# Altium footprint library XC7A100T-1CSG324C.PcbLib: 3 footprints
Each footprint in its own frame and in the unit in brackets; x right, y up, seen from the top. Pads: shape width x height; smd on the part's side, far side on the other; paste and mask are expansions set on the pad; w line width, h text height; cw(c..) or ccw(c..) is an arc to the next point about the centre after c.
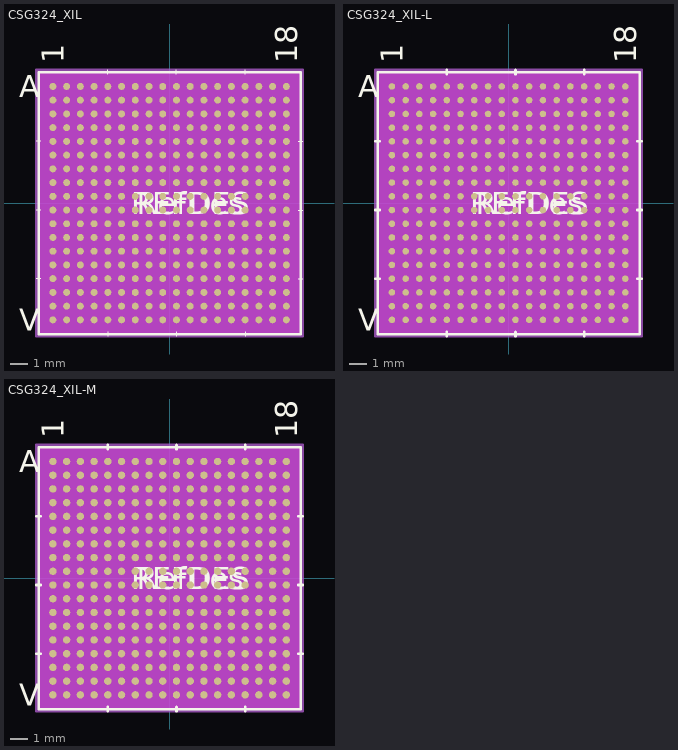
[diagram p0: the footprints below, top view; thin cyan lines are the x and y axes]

## CSG324_XIL [mm]
pads (324):
  round 0.406 smd paste+0 mask+0: A1(-6.8,6.8) A2(-6,6.8) A3(-5.2,6.8) A4(-4.4,6.8) A5(-3.6,6.8) A6(-2.8,6.8) A7(-2,6.8) A8(-1.2,6.8) A9(-0.4,6.8) A10(0.4,6.8) A11(1.2,6.8) A12(2,6.8) A13(2.8,6.8) A14(3.6,6.8) A15(4.4,6.8) A16(5.2,6.8) A17(6,6.8) A18(6.8,6.8) B1(-6.8,6) B2(-6,6) B3(-5.2,6) B4(-4.4,6) B5(-3.6,6) B6(-2.8,6) B7(-2,6) B8(-1.2,6) B9(-0.4,6) B10(0.4,6) B11(1.2,6) B12(2,6) B13(2.8,6) B14(3.6,6) B15(4.4,6) B16(5.2,6) B17(6,6) B18(6.8,6) C1(-6.8,5.2) C2(-6,5.2) C3(-5.2,5.2) C4(-4.4,5.2) C5(-3.6,5.2) C6(-2.8,5.2) C7(-2,5.2) C8(-1.2,5.2) C9(-0.4,5.2) C10(0.4,5.2) C11(1.2,5.2) C12(2,5.2) C13(2.8,5.2) C14(3.6,5.2) C15(4.4,5.2) C16(5.2,5.2) C17(6,5.2) C18(6.8,5.2) D1(-6.8,4.4) D2(-6,4.4) D3(-5.2,4.4) D4(-4.4,4.4) D5(-3.6,4.4) D6(-2.8,4.4) D7(-2,4.4) D8(-1.2,4.4) D9(-0.4,4.4) D10(0.4,4.4) D11(1.2,4.4) D12(2,4.4) D13(2.8,4.4) D14(3.6,4.4) D15(4.4,4.4) D16(5.2,4.4) D17(6,4.4) D18(6.8,4.4) E1(-6.8,3.6) E2(-6,3.6) E3(-5.2,3.6) E4(-4.4,3.6) E5(-3.6,3.6) E6(-2.8,3.6) E7(-2,3.6) E8(-1.2,3.6) E9(-0.4,3.6) E10(0.4,3.6) E11(1.2,3.6) E12(2,3.6) E13(2.8,3.6) E14(3.6,3.6) E15(4.4,3.6) E16(5.2,3.6) E17(6,3.6) E18(6.8,3.6) F1(-6.8,2.8) F2(-6,2.8) F3(-5.2,2.8) F4(-4.4,2.8) F5(-3.6,2.8) F6(-2.8,2.8) F7(-2,2.8) F8(-1.2,2.8) F9(-0.4,2.8) F10(0.4,2.8) F11(1.2,2.8) F12(2,2.8) F13(2.8,2.8) F14(3.6,2.8) F15(4.4,2.8) F16(5.2,2.8) F17(6,2.8) F18(6.8,2.8) G1(-6.8,2) G2(-6,2) G3(-5.2,2) G4(-4.4,2) G5(-3.6,2) G6(-2.8,2) G7(-2,2) G8(-1.2,2) G9(-0.4,2) G10(0.4,2) G11(1.2,2) G12(2,2) G13(2.8,2) G14(3.6,2) G15(4.4,2) G16(5.2,2) G17(6,2) G18(6.8,2) H1(-6.8,1.2) H2(-6,1.2) H3(-5.2,1.2) H4(-4.4,1.2) H5(-3.6,1.2) H6(-2.8,1.2) H7(-2,1.2) H8(-1.2,1.2) H9(-0.4,1.2) H10(0.4,1.2) H11(1.2,1.2) H12(2,1.2) H13(2.8,1.2) H14(3.6,1.2) H15(4.4,1.2) H16(5.2,1.2) H17(6,1.2) H18(6.8,1.2) J1(-6.8,0.4) J2(-6,0.4) J3(-5.2,0.4) J4(-4.4,0.4) J5(-3.6,0.4) J6(-2.8,0.4) J7(-2,0.4) J8(-1.2,0.4) J9(-0.4,0.4) J10(0.4,0.4) J11(1.2,0.4) J12(2,0.4) J13(2.8,0.4) J14(3.6,0.4) J15(4.4,0.4) J16(5.2,0.4) J17(6,0.4) J18(6.8,0.4) K1(-6.8,-0.4) K2(-6,-0.4) K3(-5.2,-0.4) K4(-4.4,-0.4) K5(-3.6,-0.4) K6(-2.8,-0.4) K7(-2,-0.4) K8(-1.2,-0.4) K9(-0.4,-0.4) K10(0.4,-0.4) K11(1.2,-0.4) K12(2,-0.4) K13(2.8,-0.4) K14(3.6,-0.4) K15(4.4,-0.4) K16(5.2,-0.4) K17(6,-0.4) K18(6.8,-0.4) L1(-6.8,-1.2) L2(-6,-1.2) L3(-5.2,-1.2) L4(-4.4,-1.2) L5(-3.6,-1.2) L6(-2.8,-1.2) L7(-2,-1.2) L8(-1.2,-1.2) L9(-0.4,-1.2) L10(0.4,-1.2) L11(1.2,-1.2) L12(2,-1.2) L13(2.8,-1.2) L14(3.6,-1.2) L15(4.4,-1.2) L16(5.2,-1.2) L17(6,-1.2) L18(6.8,-1.2) M1(-6.8,-2) M2(-6,-2) M3(-5.2,-2) M4(-4.4,-2) M5(-3.6,-2) M6(-2.8,-2) M7(-2,-2) M8(-1.2,-2) M9(-0.4,-2) M10(0.4,-2) M11(1.2,-2) M12(2,-2) M13(2.8,-2) M14(3.6,-2) M15(4.4,-2) M16(5.2,-2) M17(6,-2) M18(6.8,-2) N1(-6.8,-2.8) N2(-6,-2.8) N3(-5.2,-2.8) N4(-4.4,-2.8) N5(-3.6,-2.8) N6(-2.8,-2.8) N7(-2,-2.8) N8(-1.2,-2.8) N9(-0.4,-2.8) N10(0.4,-2.8) N11(1.2,-2.8) N12(2,-2.8) N13(2.8,-2.8) N14(3.6,-2.8) N15(4.4,-2.8) N16(5.2,-2.8) N17(6,-2.8) N18(6.8,-2.8) P1(-6.8,-3.6) P2(-6,-3.6) P3(-5.2,-3.6) P4(-4.4,-3.6) P5(-3.6,-3.6) P6(-2.8,-3.6) P7(-2,-3.6) P8(-1.2,-3.6) P9(-0.4,-3.6) P10(0.4,-3.6) P11(1.2,-3.6) P12(2,-3.6) P13(2.8,-3.6) P14(3.6,-3.6) P15(4.4,-3.6) P16(5.2,-3.6) P17(6,-3.6) P18(6.8,-3.6) R1(-6.8,-4.4) R2(-6,-4.4) R3(-5.2,-4.4) R4(-4.4,-4.4) R5(-3.6,-4.4) R6(-2.8,-4.4) R7(-2,-4.4) R8(-1.2,-4.4) R9(-0.4,-4.4) R10(0.4,-4.4) R11(1.2,-4.4) R12(2,-4.4) R13(2.8,-4.4) R14(3.6,-4.4) R15(4.4,-4.4) R16(5.2,-4.4) R17(6,-4.4) R18(6.8,-4.4) T1(-6.8,-5.2) T2(-6,-5.2) T3(-5.2,-5.2) T4(-4.4,-5.2) T5(-3.6,-5.2) T6(-2.8,-5.2) T7(-2,-5.2) T8(-1.2,-5.2) T9(-0.4,-5.2) T10(0.4,-5.2) T11(1.2,-5.2) T12(2,-5.2) T13(2.8,-5.2) T14(3.6,-5.2) T15(4.4,-5.2) T16(5.2,-5.2) T17(6,-5.2) T18(6.8,-5.2) U1(-6.8,-6) U2(-6,-6) U3(-5.2,-6) U4(-4.4,-6) U5(-3.6,-6) U6(-2.8,-6) U7(-2,-6) U8(-1.2,-6) U9(-0.4,-6) U10(0.4,-6) U11(1.2,-6) U12(2,-6) U13(2.8,-6) U14(3.6,-6) U15(4.4,-6) U16(5.2,-6) U17(6,-6) U18(6.8,-6) V1(-6.8,-6.8) V2(-6,-6.8) V3(-5.2,-6.8) V4(-4.4,-6.8) V5(-3.6,-6.8) V6(-2.8,-6.8) V7(-2,-6.8) V8(-1.2,-6.8) V9(-0.4,-6.8) V10(0.4,-6.8) V11(1.2,-6.8) V12(2,-6.8) V13(2.8,-6.8) V14(3.6,-6.8) V15(4.4,-6.8) V16(5.2,-6.8) V17(6,-6.8) V18(6.8,-6.8)
Top Overlay:
  lines w0.025: -7.76,-4.4 -7.506,-4.4 ; -7.76,-0.4 -7.506,-0.4 ; -7.76,3.6 -7.506,3.6 ; -3.6,-7.76 -3.6,-7.506 ; -3.6,7.506 -3.6,7.76 ; 0.4,-7.76 0.4,-7.506 ; 0.4,7.506 0.4,7.76 ; 4.4,-7.76 4.4,-7.506 ; 4.4,7.506 4.4,7.76 ; 7.506,-4.4 7.76,-4.4 ; 7.506,-0.4 7.76,-0.4 ; 7.506,3.6 7.76,3.6
  lines w0.152: -7.633,-7.633 7.633,-7.633 7.633,7.633 -7.633,7.633 -7.633,-7.633
  text "A" at -8.776,6.165 h1.27
  text "V" at -8.776,-7.435 h1.27
  text "1" at -6.165,8.141 h1.27
  text "18" at 7.435,8.141 h1.27
  text "RefDes" at -1.905,-0.635 h1.27
  text "REFDES" at -2.222,-0.635 h1.27
Bottom Overlay:
  text "A" at -8.141,6.165 h1.27
  text "V" at -8.141,-7.435 h1.27
  text "1" at -7.435,8.141 h1.27
  text "18" at 6.165,8.141 h1.27
Keep-Out Layer:
  region: -7.644,-7.644 -7.644,7.644 7.644,7.644 7.644,-7.644
Mechanical 13:
  lines w0.025: -7.506,7.106 -7.106,7.506 ; -7.506,-7.506 7.506,-7.506 7.506,7.506 -7.506,7.506 -7.506,-7.506
  text "A" at -8.776,6.165 h1.27
  text "V" at -8.776,-7.435 h1.27
  text "1" at -6.165,8.141 h1.27
  text "18" at 7.435,8.141 h1.27
  text "RefDes2" at -2.222,-0.635 h1.27
Mechanical 15:
  region: 7.76,-7.76 -7.76,-7.76 -7.76,7.76 7.76,7.76
  lines w0.152: -7.76,-7.76 -7.76,7.76 7.76,7.76 7.76,-7.76 -7.76,-7.76
3D body "CSG324_XIL.step": height 1.5, standoff 0, extent -7.506,-7.506 7.506,7.506

## CSG324_XIL-L [mm]
pads (324):
  round 0.381 smd paste+0 mask+0: A1(-6.8,6.8) A2(-6,6.8) A3(-5.2,6.8) A4(-4.4,6.8) A5(-3.6,6.8) A6(-2.8,6.8) A7(-2,6.8) A8(-1.2,6.8) A9(-0.4,6.8) A10(0.4,6.8) A11(1.2,6.8) A12(2,6.8) A13(2.8,6.8) A14(3.6,6.8) A15(4.4,6.8) A16(5.2,6.8) A17(6,6.8) A18(6.8,6.8) B1(-6.8,6) B2(-6,6) B3(-5.2,6) B4(-4.4,6) B5(-3.6,6) B6(-2.8,6) B7(-2,6) B8(-1.2,6) B9(-0.4,6) B10(0.4,6) B11(1.2,6) B12(2,6) B13(2.8,6) B14(3.6,6) B15(4.4,6) B16(5.2,6) B17(6,6) B18(6.8,6) C1(-6.8,5.2) C2(-6,5.2) C3(-5.2,5.2) C4(-4.4,5.2) C5(-3.6,5.2) C6(-2.8,5.2) C7(-2,5.2) C8(-1.2,5.2) C9(-0.4,5.2) C10(0.4,5.2) C11(1.2,5.2) C12(2,5.2) C13(2.8,5.2) C14(3.6,5.2) C15(4.4,5.2) C16(5.2,5.2) C17(6,5.2) C18(6.8,5.2) D1(-6.8,4.4) D2(-6,4.4) D3(-5.2,4.4) D4(-4.4,4.4) D5(-3.6,4.4) D6(-2.8,4.4) D7(-2,4.4) D8(-1.2,4.4) D9(-0.4,4.4) D10(0.4,4.4) D11(1.2,4.4) D12(2,4.4) D13(2.8,4.4) D14(3.6,4.4) D15(4.4,4.4) D16(5.2,4.4) D17(6,4.4) D18(6.8,4.4) E1(-6.8,3.6) E2(-6,3.6) E3(-5.2,3.6) E4(-4.4,3.6) E5(-3.6,3.6) E6(-2.8,3.6) E7(-2,3.6) E8(-1.2,3.6) E9(-0.4,3.6) E10(0.4,3.6) E11(1.2,3.6) E12(2,3.6) E13(2.8,3.6) E14(3.6,3.6) E15(4.4,3.6) E16(5.2,3.6) E17(6,3.6) E18(6.8,3.6) F1(-6.8,2.8) F2(-6,2.8) F3(-5.2,2.8) F4(-4.4,2.8) F5(-3.6,2.8) F6(-2.8,2.8) F7(-2,2.8) F8(-1.2,2.8) F9(-0.4,2.8) F10(0.4,2.8) F11(1.2,2.8) F12(2,2.8) F13(2.8,2.8) F14(3.6,2.8) F15(4.4,2.8) F16(5.2,2.8) F17(6,2.8) F18(6.8,2.8) G1(-6.8,2) G2(-6,2) G3(-5.2,2) G4(-4.4,2) G5(-3.6,2) G6(-2.8,2) G7(-2,2) G8(-1.2,2) G9(-0.4,2) G10(0.4,2) G11(1.2,2) G12(2,2) G13(2.8,2) G14(3.6,2) G15(4.4,2) G16(5.2,2) G17(6,2) G18(6.8,2) H1(-6.8,1.2) H2(-6,1.2) H3(-5.2,1.2) H4(-4.4,1.2) H5(-3.6,1.2) H6(-2.8,1.2) H7(-2,1.2) H8(-1.2,1.2) H9(-0.4,1.2) H10(0.4,1.2) H11(1.2,1.2) H12(2,1.2) H13(2.8,1.2) H14(3.6,1.2) H15(4.4,1.2) H16(5.2,1.2) H17(6,1.2) H18(6.8,1.2) J1(-6.8,0.4) J2(-6,0.4) J3(-5.2,0.4) J4(-4.4,0.4) J5(-3.6,0.4) J6(-2.8,0.4) J7(-2,0.4) J8(-1.2,0.4) J9(-0.4,0.4) J10(0.4,0.4) J11(1.2,0.4) J12(2,0.4) J13(2.8,0.4) J14(3.6,0.4) J15(4.4,0.4) J16(5.2,0.4) J17(6,0.4) J18(6.8,0.4) K1(-6.8,-0.4) K2(-6,-0.4) K3(-5.2,-0.4) K4(-4.4,-0.4) K5(-3.6,-0.4) K6(-2.8,-0.4) K7(-2,-0.4) K8(-1.2,-0.4) K9(-0.4,-0.4) K10(0.4,-0.4) K11(1.2,-0.4) K12(2,-0.4) K13(2.8,-0.4) K14(3.6,-0.4) K15(4.4,-0.4) K16(5.2,-0.4) K17(6,-0.4) K18(6.8,-0.4) L1(-6.8,-1.2) L2(-6,-1.2) L3(-5.2,-1.2) L4(-4.4,-1.2) L5(-3.6,-1.2) L6(-2.8,-1.2) L7(-2,-1.2) L8(-1.2,-1.2) L9(-0.4,-1.2) L10(0.4,-1.2) L11(1.2,-1.2) L12(2,-1.2) L13(2.8,-1.2) L14(3.6,-1.2) L15(4.4,-1.2) L16(5.2,-1.2) L17(6,-1.2) L18(6.8,-1.2) M1(-6.8,-2) M2(-6,-2) M3(-5.2,-2) M4(-4.4,-2) M5(-3.6,-2) M6(-2.8,-2) M7(-2,-2) M8(-1.2,-2) M9(-0.4,-2) M10(0.4,-2) M11(1.2,-2) M12(2,-2) M13(2.8,-2) M14(3.6,-2) M15(4.4,-2) M16(5.2,-2) M17(6,-2) M18(6.8,-2) N1(-6.8,-2.8) N2(-6,-2.8) N3(-5.2,-2.8) N4(-4.4,-2.8) N5(-3.6,-2.8) N6(-2.8,-2.8) N7(-2,-2.8) N8(-1.2,-2.8) N9(-0.4,-2.8) N10(0.4,-2.8) N11(1.2,-2.8) N12(2,-2.8) N13(2.8,-2.8) N14(3.6,-2.8) N15(4.4,-2.8) N16(5.2,-2.8) N17(6,-2.8) N18(6.8,-2.8) P1(-6.8,-3.6) P2(-6,-3.6) P3(-5.2,-3.6) P4(-4.4,-3.6) P5(-3.6,-3.6) P6(-2.8,-3.6) P7(-2,-3.6) P8(-1.2,-3.6) P9(-0.4,-3.6) P10(0.4,-3.6) P11(1.2,-3.6) P12(2,-3.6) P13(2.8,-3.6) P14(3.6,-3.6) P15(4.4,-3.6) P16(5.2,-3.6) P17(6,-3.6) P18(6.8,-3.6) R1(-6.8,-4.4) R2(-6,-4.4) R3(-5.2,-4.4) R4(-4.4,-4.4) R5(-3.6,-4.4) R6(-2.8,-4.4) R7(-2,-4.4) R8(-1.2,-4.4) R9(-0.4,-4.4) R10(0.4,-4.4) R11(1.2,-4.4) R12(2,-4.4) R13(2.8,-4.4) R14(3.6,-4.4) R15(4.4,-4.4) R16(5.2,-4.4) R17(6,-4.4) R18(6.8,-4.4) T1(-6.8,-5.2) T2(-6,-5.2) T3(-5.2,-5.2) T4(-4.4,-5.2) T5(-3.6,-5.2) T6(-2.8,-5.2) T7(-2,-5.2) T8(-1.2,-5.2) T9(-0.4,-5.2) T10(0.4,-5.2) T11(1.2,-5.2) T12(2,-5.2) T13(2.8,-5.2) T14(3.6,-5.2) T15(4.4,-5.2) T16(5.2,-5.2) T17(6,-5.2) T18(6.8,-5.2) U1(-6.8,-6) U2(-6,-6) U3(-5.2,-6) U4(-4.4,-6) U5(-3.6,-6) U6(-2.8,-6) U7(-2,-6) U8(-1.2,-6) U9(-0.4,-6) U10(0.4,-6) U11(1.2,-6) U12(2,-6) U13(2.8,-6) U14(3.6,-6) U15(4.4,-6) U16(5.2,-6) U17(6,-6) U18(6.8,-6) V1(-6.8,-6.8) V2(-6,-6.8) V3(-5.2,-6.8) V4(-4.4,-6.8) V5(-3.6,-6.8) V6(-2.8,-6.8) V7(-2,-6.8) V8(-1.2,-6.8) V9(-0.4,-6.8) V10(0.4,-6.8) V11(1.2,-6.8) V12(2,-6.8) V13(2.8,-6.8) V14(3.6,-6.8) V15(4.4,-6.8) V16(5.2,-6.8) V17(6,-6.8) V18(6.8,-6.8)
Top Overlay:
  lines w0.152: -7.76,-4.4 -7.506,-4.4 ; -7.76,-0.4 -7.506,-0.4 ; -7.76,3.6 -7.506,3.6 ; -3.6,-7.76 -3.6,-7.506 ; -3.6,7.506 -3.6,7.76 ; 0.4,-7.76 0.4,-7.506 ; 0.4,7.506 0.4,7.76 ; 4.4,-7.76 4.4,-7.506 ; 4.4,7.506 4.4,7.76 ; 7.506,-4.4 7.76,-4.4 ; 7.506,-0.4 7.76,-0.4 ; 7.506,3.6 7.76,3.6 ; -7.633,-7.633 7.633,-7.633 7.633,7.633 -7.633,7.633 -7.633,-7.633
  text "A" at -8.776,6.165 h1.27
  text "V" at -8.776,-7.435 h1.27
  text "1" at -6.165,8.141 h1.27
  text "18" at 7.435,8.141 h1.27
  text "RefDes" at -1.905,-0.635 h1.27
  text "REFDES" at -2.222,-0.635 h1.27
Bottom Overlay:
  text "A" at -8.141,6.165 h1.27
  text "V" at -8.141,-7.435 h1.27
  text "1" at -7.435,8.141 h1.27
  text "18" at 6.165,8.141 h1.27
Keep-Out Layer:
  region: -7.644,-7.644 -7.644,7.644 7.644,7.644 7.644,-7.644
Mechanical 13:
  lines w0.025: -7.506,7.106 -7.106,7.506 ; -7.506,-7.506 7.506,-7.506 7.506,7.506 -7.506,7.506 -7.506,-7.506
  text "A" at -8.776,6.165 h1.27
  text "V" at -8.776,-7.435 h1.27
  text "1" at -6.165,8.141 h1.27
  text "18" at 7.435,8.141 h1.27
  text "RefDes2" at -2.222,-0.635 h1.27
Mechanical 15:
  region: 7.76,-7.76 -7.76,-7.76 -7.76,7.76 7.76,7.76
  lines w0.152: -7.76,-7.76 -7.76,7.76 7.76,7.76 7.76,-7.76 -7.76,-7.76
3D body "CSG324_XIL.step": height 1.5, standoff 0, extent -7.506,-7.506 7.506,7.506

## CSG324_XIL-M [mm]
pads (324):
  round 0.432 smd paste+0 mask+0: A1(-6.8,6.8) A2(-6,6.8) A3(-5.2,6.8) A4(-4.4,6.8) A5(-3.6,6.8) A6(-2.8,6.8) A7(-2,6.8) A8(-1.2,6.8) A9(-0.4,6.8) A10(0.4,6.8) A11(1.2,6.8) A12(2,6.8) A13(2.8,6.8) A14(3.6,6.8) A15(4.4,6.8) A16(5.2,6.8) A17(6,6.8) A18(6.8,6.8) B1(-6.8,6) B2(-6,6) B3(-5.2,6) B4(-4.4,6) B5(-3.6,6) B6(-2.8,6) B7(-2,6) B8(-1.2,6) B9(-0.4,6) B10(0.4,6) B11(1.2,6) B12(2,6) B13(2.8,6) B14(3.6,6) B15(4.4,6) B16(5.2,6) B17(6,6) B18(6.8,6) C1(-6.8,5.2) C2(-6,5.2) C3(-5.2,5.2) C4(-4.4,5.2) C5(-3.6,5.2) C6(-2.8,5.2) C7(-2,5.2) C8(-1.2,5.2) C9(-0.4,5.2) C10(0.4,5.2) C11(1.2,5.2) C12(2,5.2) C13(2.8,5.2) C14(3.6,5.2) C15(4.4,5.2) C16(5.2,5.2) C17(6,5.2) C18(6.8,5.2) D1(-6.8,4.4) D2(-6,4.4) D3(-5.2,4.4) D4(-4.4,4.4) D5(-3.6,4.4) D6(-2.8,4.4) D7(-2,4.4) D8(-1.2,4.4) D9(-0.4,4.4) D10(0.4,4.4) D11(1.2,4.4) D12(2,4.4) D13(2.8,4.4) D14(3.6,4.4) D15(4.4,4.4) D16(5.2,4.4) D17(6,4.4) D18(6.8,4.4) E1(-6.8,3.6) E2(-6,3.6) E3(-5.2,3.6) E4(-4.4,3.6) E5(-3.6,3.6) E6(-2.8,3.6) E7(-2,3.6) E8(-1.2,3.6) E9(-0.4,3.6) E10(0.4,3.6) E11(1.2,3.6) E12(2,3.6) E13(2.8,3.6) E14(3.6,3.6) E15(4.4,3.6) E16(5.2,3.6) E17(6,3.6) E18(6.8,3.6) F1(-6.8,2.8) F2(-6,2.8) F3(-5.2,2.8) F4(-4.4,2.8) F5(-3.6,2.8) F6(-2.8,2.8) F7(-2,2.8) F8(-1.2,2.8) F9(-0.4,2.8) F10(0.4,2.8) F11(1.2,2.8) F12(2,2.8) F13(2.8,2.8) F14(3.6,2.8) F15(4.4,2.8) F16(5.2,2.8) F17(6,2.8) F18(6.8,2.8) G1(-6.8,2) G2(-6,2) G3(-5.2,2) G4(-4.4,2) G5(-3.6,2) G6(-2.8,2) G7(-2,2) G8(-1.2,2) G9(-0.4,2) G10(0.4,2) G11(1.2,2) G12(2,2) G13(2.8,2) G14(3.6,2) G15(4.4,2) G16(5.2,2) G17(6,2) G18(6.8,2) H1(-6.8,1.2) H2(-6,1.2) H3(-5.2,1.2) H4(-4.4,1.2) H5(-3.6,1.2) H6(-2.8,1.2) H7(-2,1.2) H8(-1.2,1.2) H9(-0.4,1.2) H10(0.4,1.2) H11(1.2,1.2) H12(2,1.2) H13(2.8,1.2) H14(3.6,1.2) H15(4.4,1.2) H16(5.2,1.2) H17(6,1.2) H18(6.8,1.2) J1(-6.8,0.4) J2(-6,0.4) J3(-5.2,0.4) J4(-4.4,0.4) J5(-3.6,0.4) J6(-2.8,0.4) J7(-2,0.4) J8(-1.2,0.4) J9(-0.4,0.4) J10(0.4,0.4) J11(1.2,0.4) J12(2,0.4) J13(2.8,0.4) J14(3.6,0.4) J15(4.4,0.4) J16(5.2,0.4) J17(6,0.4) J18(6.8,0.4) K1(-6.8,-0.4) K2(-6,-0.4) K3(-5.2,-0.4) K4(-4.4,-0.4) K5(-3.6,-0.4) K6(-2.8,-0.4) K7(-2,-0.4) K8(-1.2,-0.4) K9(-0.4,-0.4) K10(0.4,-0.4) K11(1.2,-0.4) K12(2,-0.4) K13(2.8,-0.4) K14(3.6,-0.4) K15(4.4,-0.4) K16(5.2,-0.4) K17(6,-0.4) K18(6.8,-0.4) L1(-6.8,-1.2) L2(-6,-1.2) L3(-5.2,-1.2) L4(-4.4,-1.2) L5(-3.6,-1.2) L6(-2.8,-1.2) L7(-2,-1.2) L8(-1.2,-1.2) L9(-0.4,-1.2) L10(0.4,-1.2) L11(1.2,-1.2) L12(2,-1.2) L13(2.8,-1.2) L14(3.6,-1.2) L15(4.4,-1.2) L16(5.2,-1.2) L17(6,-1.2) L18(6.8,-1.2) M1(-6.8,-2) M2(-6,-2) M3(-5.2,-2) M4(-4.4,-2) M5(-3.6,-2) M6(-2.8,-2) M7(-2,-2) M8(-1.2,-2) M9(-0.4,-2) M10(0.4,-2) M11(1.2,-2) M12(2,-2) M13(2.8,-2) M14(3.6,-2) M15(4.4,-2) M16(5.2,-2) M17(6,-2) M18(6.8,-2) N1(-6.8,-2.8) N2(-6,-2.8) N3(-5.2,-2.8) N4(-4.4,-2.8) N5(-3.6,-2.8) N6(-2.8,-2.8) N7(-2,-2.8) N8(-1.2,-2.8) N9(-0.4,-2.8) N10(0.4,-2.8) N11(1.2,-2.8) N12(2,-2.8) N13(2.8,-2.8) N14(3.6,-2.8) N15(4.4,-2.8) N16(5.2,-2.8) N17(6,-2.8) N18(6.8,-2.8) P1(-6.8,-3.6) P2(-6,-3.6) P3(-5.2,-3.6) P4(-4.4,-3.6) P5(-3.6,-3.6) P6(-2.8,-3.6) P7(-2,-3.6) P8(-1.2,-3.6) P9(-0.4,-3.6) P10(0.4,-3.6) P11(1.2,-3.6) P12(2,-3.6) P13(2.8,-3.6) P14(3.6,-3.6) P15(4.4,-3.6) P16(5.2,-3.6) P17(6,-3.6) P18(6.8,-3.6) R1(-6.8,-4.4) R2(-6,-4.4) R3(-5.2,-4.4) R4(-4.4,-4.4) R5(-3.6,-4.4) R6(-2.8,-4.4) R7(-2,-4.4) R8(-1.2,-4.4) R9(-0.4,-4.4) R10(0.4,-4.4) R11(1.2,-4.4) R12(2,-4.4) R13(2.8,-4.4) R14(3.6,-4.4) R15(4.4,-4.4) R16(5.2,-4.4) R17(6,-4.4) R18(6.8,-4.4) T1(-6.8,-5.2) T2(-6,-5.2) T3(-5.2,-5.2) T4(-4.4,-5.2) T5(-3.6,-5.2) T6(-2.8,-5.2) T7(-2,-5.2) T8(-1.2,-5.2) T9(-0.4,-5.2) T10(0.4,-5.2) T11(1.2,-5.2) T12(2,-5.2) T13(2.8,-5.2) T14(3.6,-5.2) T15(4.4,-5.2) T16(5.2,-5.2) T17(6,-5.2) T18(6.8,-5.2) U1(-6.8,-6) U2(-6,-6) U3(-5.2,-6) U4(-4.4,-6) U5(-3.6,-6) U6(-2.8,-6) U7(-2,-6) U8(-1.2,-6) U9(-0.4,-6) U10(0.4,-6) U11(1.2,-6) U12(2,-6) U13(2.8,-6) U14(3.6,-6) U15(4.4,-6) U16(5.2,-6) U17(6,-6) U18(6.8,-6) V1(-6.8,-6.8) V2(-6,-6.8) V3(-5.2,-6.8) V4(-4.4,-6.8) V5(-3.6,-6.8) V6(-2.8,-6.8) V7(-2,-6.8) V8(-1.2,-6.8) V9(-0.4,-6.8) V10(0.4,-6.8) V11(1.2,-6.8) V12(2,-6.8) V13(2.8,-6.8) V14(3.6,-6.8) V15(4.4,-6.8) V16(5.2,-6.8) V17(6,-6.8) V18(6.8,-6.8)
Top Overlay:
  lines w0.152: -7.76,-4.4 -7.506,-4.4 ; -7.76,-0.4 -7.506,-0.4 ; -7.76,3.6 -7.506,3.6 ; -3.6,-7.76 -3.6,-7.506 ; -3.6,7.506 -3.6,7.76 ; 0.4,-7.76 0.4,-7.506 ; 0.4,7.506 0.4,7.76 ; 4.4,-7.76 4.4,-7.506 ; 4.4,7.506 4.4,7.76 ; 7.506,-4.4 7.76,-4.4 ; 7.506,-0.4 7.76,-0.4 ; 7.506,3.6 7.76,3.6 ; -7.633,-7.633 7.633,-7.633 7.633,7.633 -7.633,7.633 -7.633,-7.633
  text "A" at -8.776,6.165 h1.27
  text "V" at -8.776,-7.435 h1.27
  text "1" at -6.165,8.141 h1.27
  text "18" at 7.435,8.141 h1.27
  text "RefDes" at -1.905,-0.635 h1.27
  text "REFDES" at -2.222,-0.635 h1.27
Bottom Overlay:
  text "A" at -8.141,6.165 h1.27
  text "V" at -8.141,-7.435 h1.27
  text "1" at -7.435,8.141 h1.27
  text "18" at 6.165,8.141 h1.27
Keep-Out Layer:
  region: -7.644,-7.644 -7.644,7.644 7.644,7.644 7.644,-7.644
Mechanical 13:
  lines w0.025: -7.506,7.106 -7.106,7.506 ; -7.506,-7.506 7.506,-7.506 7.506,7.506 -7.506,7.506 -7.506,-7.506
  text "A" at -8.776,6.165 h1.27
  text "V" at -8.776,-7.435 h1.27
  text "1" at -6.165,8.141 h1.27
  text "18" at 7.435,8.141 h1.27
  text "RefDes2" at -2.222,-0.635 h1.27
Mechanical 15:
  region: 7.76,-7.76 -7.76,-7.76 -7.76,7.76 7.76,7.76
  lines w0.152: -7.76,-7.76 -7.76,7.76 7.76,7.76 7.76,-7.76 -7.76,-7.76
3D body "CSG324_XIL.step": height 1.5, standoff 0, extent -7.506,-7.506 7.506,7.506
